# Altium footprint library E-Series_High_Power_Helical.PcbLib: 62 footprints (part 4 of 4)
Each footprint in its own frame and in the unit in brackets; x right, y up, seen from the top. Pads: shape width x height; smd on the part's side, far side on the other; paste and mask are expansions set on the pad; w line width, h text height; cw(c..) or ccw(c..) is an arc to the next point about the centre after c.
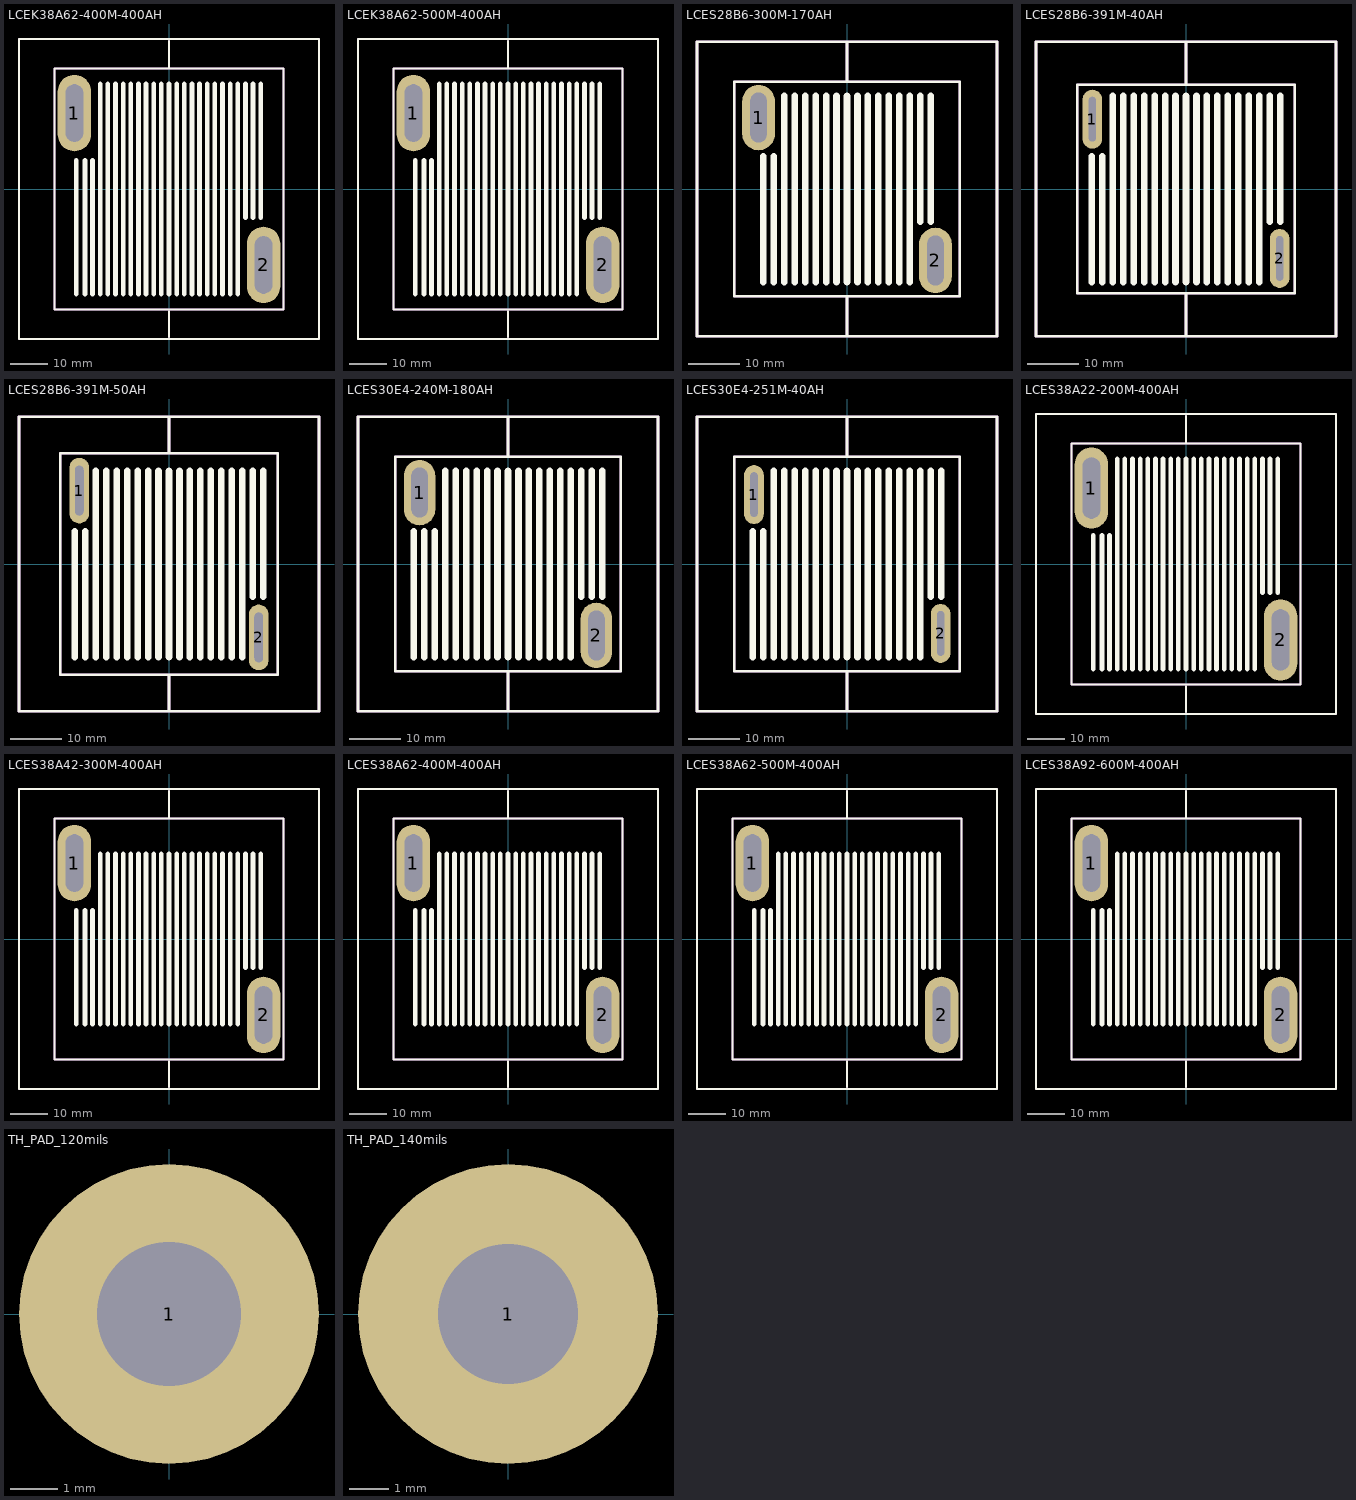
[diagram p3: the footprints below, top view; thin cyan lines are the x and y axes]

## LCEK38A62-400M-400AH [mil]
pads (2):
  oval 350x800 hole 185 slot 600 at 90 deg: 1(-990,795) 2(990,-795)
Top Overlay:
  lines w19.68: 0,-1550 0,-1280 ; 0,1260 0,1550 ; -1570,-1570 -1570,1570 1570,1570 1570,-1570 -1570,-1570 ; -1200,-1260 -1200,1260 1200,1260 1200,-1260 -1200,-1260
  lines w50: -970,-1100 -970,300 ; -880,-1100 -880,300 ; -800,-1100 -800,300 ; -720,-1100 -720,1100 ; -640,-1100 -640,1100 ; -560,-1100 -560,1100 ; -480,-1100 -480,1100 ; -400,-1100 -400,1100 ; -320,-1100 -320,1100 ; -240,-1100 -240,1100 ; -160,-1100 -160,1100 ; -80,-1100 -80,1100 ; 0,-1100 0,1100 ; 80,-1100 80,1100 ; 160,-1100 160,1100 ; 240,-1100 240,1100 ; 320,-1100 320,1100 ; 400,-1100 400,1100 ; 480,-1100 480,1100 ; 560,-1100 560,1100 ; 640,-1100 640,1100 ; 720,-1100 720,1100 ; 800,-300 800,1100 ; 880,-300 880,1100 ; 960,-300 960,1100
Components Top Assy:
  lines w19.68: 0,-1550 0,-1280 ; 0,1260 0,1550 ; -1570,-1570 1570,-1570 1570,1570 -1570,1570 -1570,-1570 ; -1200,-1260 1200,-1260 1200,1260 -1200,1260 -1200,-1260
  text "'.Designator'" at -938.15,-44.83 h400

## LCEK38A62-500M-400AH [mil]
pads (2):
  oval 350x800 hole 185 slot 600 at 90 deg: 1(-990,795) 2(990,-795)
Top Overlay:
  lines w19.68: 0,-1550 0,-1280 ; 0,1260 0,1550 ; -1570,-1570 1570,-1570 1570,1570 -1570,1570 -1570,-1570 ; -1200,-1260 1200,-1260 1200,1260 -1200,1260 -1200,-1260
  lines w50: -970,-1100 -970,300 ; -880,-1100 -880,300 ; -800,-1100 -800,300 ; -720,-1100 -720,1100 ; -640,-1100 -640,1100 ; -560,-1100 -560,1100 ; -480,-1100 -480,1100 ; -400,-1100 -400,1100 ; -320,-1100 -320,1100 ; -240,-1100 -240,1100 ; -160,-1100 -160,1100 ; -80,-1100 -80,1100 ; 0,-1100 0,1100 ; 80,-1100 80,1100 ; 160,-1100 160,1100 ; 240,-1100 240,1100 ; 320,-1100 320,1100 ; 400,-1100 400,1100 ; 480,-1100 480,1100 ; 560,-1100 560,1100 ; 640,-1100 640,1100 ; 720,-1100 720,1100 ; 800,-300 800,1100 ; 880,-300 880,1100 ; 960,-300 960,1100
Components Top Assy:
  lines w19.68: 0,-1550 0,-1280 ; 0,1260 0,1550 ; -1570,-1570 1570,-1570 1570,1570 -1570,1570 -1570,-1570 ; -1200,-1260 1200,-1260 1200,1260 -1200,1260 -1200,-1260
  text "'.Designator'" at -938.15,-44.83 h400

## LCES28B6-300M-170AH [mil]
pads (2):
  oval 250x500 hole 125 slot 380 at 90 deg: 1(-675,545) 2(675,-545)
Top Overlay:
  lines w19.68: 0,-1120 0,-820 ; 0,820 0,1120 ; -1145,-1125 -1145,1125 1145,1125 1145,-1125 -1145,-1125 ; -860,-820 -860,820 860,820 860,-820 -860,-820
  lines w50: -640,-710 -640,250 ; -560,-710 -560,250 ; -480,-710 -480,710 ; -400,-710 -400,710 ; -320,-710 -320,710 ; -240,-710 -240,710 ; -160,-710 -160,710 ; -80,-710 -80,710 ; 0,-710 0,710 ; 80,-710 80,710 ; 160,-710 160,710 ; 240,-710 240,710 ; 320,-710 320,710 ; 400,-710 400,710 ; 480,-710 480,710 ; 560,-250 560,710 ; 640,-250 640,710
Components Top Assy:
  lines w19.68: 0,-1120 0,-820 ; 0,820 0,1120 ; -1145,-1125 -1145,1125 1145,1125 1145,-1125 -1145,-1125 ; -860,-820 -860,820 860,820 860,-820 -860,-820
  text "'.Designator'" at -938.15,-44.83 h400

## LCES28B6-391M-40AH [mil]
pads (2):
  oval 150x450 hole 55 slot 340 at 90 deg: 1(-715,533) 2(715,-530)
Top Overlay:
  lines w19.68: 0,-1120 0,-795 ; 0,800 0,1120 ; -1145,-1125 1145,-1125 1145,1125 -1145,1125 -1145,-1125 ; -830,-795 830,-795 830,795 -830,795 -830,-795
  lines w50: -720,-710 -720,250 ; -640,-710 -640,250 ; -560,-710 -560,710 ; -480,-710 -480,710 ; -400,-710 -400,710 ; -320,-710 -320,710 ; -240,-710 -240,710 ; -160,-710 -160,710 ; -80,-710 -80,710 ; 0,-710 0,710 ; 80,-710 80,710 ; 160,-710 160,710 ; 240,-710 240,710 ; 320,-710 320,710 ; 400,-710 400,710 ; 480,-710 480,710 ; 560,-710 560,710 ; 640,-250 640,710 ; 720,-250 720,710
Components Top Assy:
  lines w19.68: 0,-1120 0,-795 ; 0,800 0,1120 ; -1145,-1125 1145,-1125 1145,1125 -1145,1125 -1145,-1125 ; -830,-795 830,-795 830,795 -830,795 -830,-795
  text "'.Designator'" at -950,-54.83 h400

## LCES28B6-391M-50AH [mil]
pads (2):
  oval 150x500 hole 65 slot 380 at 90 deg: 1(-685,560) 2(685,-560)
Top Overlay:
  lines w19.68: -830,840 -830,-845 830,-845 830,840 ; -830,845 830,845 ; 0,-1120 0,-845 ; 0,845 0,1120 ; -1145,-1125 -1145,1125 1145,1125 1145,-1125 -1145,-1125
  lines w50: -720,-710 -720,250 ; -640,-710 -640,250 ; -560,-710 -560,710 ; -480,-710 -480,710 ; -400,-710 -400,710 ; -320,-710 -320,710 ; -240,-710 -240,710 ; -160,-710 -160,710 ; -80,-710 -80,710 ; 0,-710 0,710 ; 80,-710 80,710 ; 160,-710 160,710 ; 240,-710 240,710 ; 320,-710 320,710 ; 400,-710 400,710 ; 480,-710 480,710 ; 560,-710 560,710 ; 640,-250 640,710 ; 720,-250 720,710
Components Top Assy:
  lines w19.68: -830,840 -830,-845 830,-845 830,840 ; -830,845 830,845 ; 0,-1120 0,-845 ; 0,845 0,1120 ; -1145,-1125 -1145,1125 1145,1125 1145,-1125 -1145,-1125
  text "'.Designator'" at -950,-54.83 h400

## LCES30E4-240M-180AH [mil]
pads (2):
  oval 240x500 hole 125 slot 380 at 90 deg: 1(-675,545) 2(675,-545)
Top Overlay:
  lines w19.68: 0,-1120 0,-820 ; 0,820 0,1120 ; -1145,-1125 -1145,1125 1145,1125 1145,-1125 -1145,-1125 ; -860,-820 -860,820 860,820 860,-820 -860,-820
  lines w50: -720,-710 -720,250 ; -640,-710 -640,250 ; -560,-710 -560,250 ; -480,-710 -480,710 ; -400,-710 -400,710 ; -320,-710 -320,710 ; -240,-710 -240,710 ; -160,-710 -160,710 ; -80,-710 -80,710 ; 0,-710 0,710 ; 80,-710 80,710 ; 160,-710 160,710 ; 240,-710 240,710 ; 320,-710 320,710 ; 400,-710 400,710 ; 480,-710 480,710 ; 560,-250 560,710 ; 640,-250 640,710 ; 720,-250 720,710
Components Top Assy:
  lines w19.68: 0,-1120 0,-820 ; 0,820 0,1120 ; -1145,-1125 1145,-1125 1145,1125 -1145,1125 -1145,-1125 ; -860,-820 860,-820 860,820 -860,820 -860,-820
  text "'.Designator'" at -938.15,-44.83 h400

## LCES30E4-251M-40AH [mil]
pads (2):
  oval 150x450 hole 55 slot 340 at 90 deg: 1(-710,530) 2(715,-530)
Top Overlay:
  lines w19.68: 0,-1120 0,-820 ; 0,820 0,1120 ; -1145,-1125 -1145,1125 1145,1125 1145,-1125 -1145,-1125 ; -860,-820 -860,820 860,820 860,-820 -860,-820
  lines w50: -720,-710 -720,250 ; -640,-710 -640,250 ; -560,-710 -560,710 ; -480,-710 -480,710 ; -400,-710 -400,710 ; -320,-710 -320,710 ; -240,-710 -240,710 ; -160,-710 -160,710 ; -80,-710 -80,710 ; 0,-710 0,710 ; 80,-710 80,710 ; 160,-710 160,710 ; 240,-710 240,710 ; 320,-710 320,710 ; 400,-710 400,710 ; 480,-710 480,710 ; 560,-710 560,710 ; 640,-250 640,710 ; 720,-250 720,710
Components Top Assy:
  lines w19.68: 0,-1120 0,-820 ; 0,820 0,1120 ; -1145,-1125 -1145,1125 1145,1125 1145,-1125 -1145,-1125 ; -860,-820 -860,820 860,820 860,-820 -860,-820
  text "'.Designator'" at -938.15,-44.83 h400

## LCES38A22-200M-400AH [mil]
pads (2):
  oval 350x850 hole 185 slot 640 at 90 deg: 1(-990,795) 2(990,-795)
Top Overlay:
  lines w19.68: 0,-1550 0,-1280 ; 0,1260 0,1550 ; -1570,-1570 1570,-1570 1570,1570 -1570,1570 -1570,-1570 ; -1200,-1260 1200,-1260 1200,1260 -1200,1260 -1200,-1260
  lines w50: -970,-1100 -970,300 ; -880,-1100 -880,300 ; -800,-1100 -800,300 ; -720,-1100 -720,1100 ; -640,-1100 -640,1100 ; -560,-1100 -560,1100 ; -480,-1100 -480,1100 ; -400,-1100 -400,1100 ; -320,-1100 -320,1100 ; -240,-1100 -240,1100 ; -160,-1100 -160,1100 ; -80,-1100 -80,1100 ; 0,-1100 0,1100 ; 80,-1100 80,1100 ; 160,-1100 160,1100 ; 240,-1100 240,1100 ; 320,-1100 320,1100 ; 400,-1100 400,1100 ; 480,-1100 480,1100 ; 560,-1100 560,1100 ; 640,-1100 640,1100 ; 720,-1100 720,1100 ; 800,-300 800,1100 ; 880,-300 880,1100 ; 960,-300 960,1100
Components Top Assy:
  lines w19.68: -1570,-1570 -1570,1570 ; -1570,-1570 1570,-1570 ; -1570,-1570 -1570,1570 ; -1570,-1570 1570,-1570 ; -1570,-1570 -1570,1570 ; -1570,-1570 1570,-1570 ; -1570,1570 1570,1570 ; -1570,1570 1570,1570 ; -1570,1570 1570,1570 ; -1200,-1260 -1200,1260 ; -1200,-1260 1200,-1260 ; -1200,-1260 -1200,1260 ; -1200,-1260 1200,-1260 ; -1200,-1260 -1200,1260 ; -1200,-1260 1200,-1260 ; -1200,1260 1200,1260 ; -1200,1260 1200,1260 ; -1200,1260 1200,1260 ; 0,-1550 0,-1280 ; 0,-1550 0,-1280 ; 0,-1550 0,-1280 ; 0,1260 0,1550 ; 0,1260 0,1550 ; 0,1260 0,1550 ; 1200,-1260 1200,1260 ; 1200,-1260 1200,1260 ; 1200,-1260 1200,1260 ; 1570,-1570 1570,1570 ; 1570,-1570 1570,1570 ; 1570,-1570 1570,1570
  text "'.Designator'" at -938.15,-44.83 h400

## LCES38A42-300M-400AH [mil]
pads (2):
  oval 350x800 hole 185 slot 600 at 90 deg: 1(-990,795) 2(990,-795)
Top Overlay:
  lines w19.68: 0,-1550 0,-1280 ; 0,1260 0,1550 ; -1570,-1570 1570,-1570 1570,1570 -1570,1570 -1570,-1570 ; -1200,-1260 1200,-1260 1200,1260 -1200,1260 -1200,-1260
  lines w50: -970,-890 -970,300 ; -880,-890 -880,300 ; -800,-890 -800,300 ; -720,-890 -720,890 ; -640,-890 -640,890 ; -560,-890 -560,890 ; -480,-890 -480,890 ; -400,-890 -400,890 ; -320,-890 -320,890 ; -240,-890 -240,890 ; -160,-890 -160,890 ; -80,-890 -80,890 ; 0,-890 0,890 ; 80,-890 80,890 ; 160,-890 160,890 ; 240,-890 240,890 ; 320,-890 320,890 ; 400,-890 400,890 ; 480,-890 480,890 ; 560,-890 560,890 ; 640,-890 640,890 ; 720,-890 720,890 ; 800,-300 800,890 ; 880,-300 880,890 ; 960,-300 960,890
Components Top Assy:
  lines w19.68: -1570,-1570 1570,-1570 ; -1570,-1570 -1570,1570 ; -1570,-1570 1570,-1570 ; -1570,-1570 -1570,1570 ; -1570,-1570 1570,-1570 ; -1570,-1570 -1570,1570 ; -1570,1570 1570,1570 ; -1570,1570 1570,1570 ; -1570,1570 1570,1570 ; -1200,-1260 1200,-1260 ; -1200,-1260 -1200,1260 ; -1200,-1260 1200,-1260 ; -1200,-1260 -1200,1260 ; -1200,-1260 1200,-1260 ; -1200,-1260 -1200,1260 ; -1200,1260 1200,1260 ; -1200,1260 1200,1260 ; -1200,1260 1200,1260 ; 0,-1550 0,-1280 ; 0,-1550 0,-1280 ; 0,-1550 0,-1280 ; 0,1260 0,1550 ; 0,1260 0,1550 ; 0,1260 0,1550 ; 1200,-1260 1200,1260 ; 1200,-1260 1200,1260 ; 1200,-1260 1200,1260 ; 1570,-1570 1570,1570 ; 1570,-1570 1570,1570 ; 1570,-1570 1570,1570
  text "'.Designator'" at -938.15,-44.83 h400

## LCES38A62-400M-400AH [mil]
pads (2):
  oval 350x800 hole 185 slot 600 at 90 deg: 1(-990,795) 2(990,-795)
Top Overlay:
  lines w19.68: -1570,-1570 1570,-1570 ; -1570,-1570 -1570,1570 ; -1570,-1570 1570,-1570 ; -1570,-1570 -1570,1570 ; -1570,-1570 1570,-1570 ; -1570,-1570 -1570,1570 ; -1570,-1570 -1570,1570 ; -1570,-1570 1570,-1570 ; -1570,1570 1570,1570 ; -1570,1570 1570,1570 ; -1570,1570 1570,1570 ; -1570,1570 1570,1570 ; -1200,-1260 1200,-1260 ; -1200,-1260 -1200,1260 ; -1200,-1260 1200,-1260 ; -1200,-1260 -1200,1260 ; -1200,-1260 1200,-1260 ; -1200,-1260 -1200,1260 ; -1200,-1260 -1200,1260 ; -1200,-1260 1200,-1260 ; -1200,1260 1200,1260 ; -1200,1260 1200,1260 ; -1200,1260 1200,1260 ; -1200,1260 1200,1260 ; 0,-1550 0,-1280 ; 0,-1550 0,-1280 ; 0,-1550 0,-1280 ; 0,-1550 0,-1280 ; 0,1260 0,1550 ; 0,1260 0,1550 ; 0,1260 0,1550 ; 0,1260 0,1550 ; 1200,-1260 1200,1260 ; 1200,-1260 1200,1260 ; 1200,-1260 1200,1260 ; 1200,-1260 1200,1260 ; 1570,-1570 1570,1570 ; 1570,-1570 1570,1570 ; 1570,-1570 1570,1570 ; 1570,-1570 1570,1570
  lines w50: -970,-890 -970,300 ; -880,-890 -880,300 ; -800,-890 -800,300 ; -720,-890 -720,890 ; -640,-890 -640,890 ; -560,-890 -560,890 ; -480,-890 -480,890 ; -400,-890 -400,890 ; -320,-890 -320,890 ; -240,-890 -240,890 ; -160,-890 -160,890 ; -80,-890 -80,890 ; 0,-890 0,890 ; 80,-890 80,890 ; 160,-890 160,890 ; 240,-890 240,890 ; 320,-890 320,890 ; 400,-890 400,890 ; 480,-890 480,890 ; 560,-890 560,890 ; 640,-890 640,890 ; 720,-890 720,890 ; 800,-300 800,890 ; 880,-300 880,890 ; 960,-300 960,890
Components Top Assy:
  lines w19.68: -1570,-1570 1570,-1570 ; -1570,-1570 -1570,1570 ; -1570,-1570 1570,-1570 ; -1570,-1570 -1570,1570 ; -1570,-1570 1570,-1570 ; -1570,-1570 -1570,1570 ; -1570,1570 1570,1570 ; -1570,1570 1570,1570 ; -1570,1570 1570,1570 ; -1200,-1260 1200,-1260 ; -1200,-1260 -1200,1260 ; -1200,-1260 1200,-1260 ; -1200,-1260 -1200,1260 ; -1200,-1260 1200,-1260 ; -1200,-1260 -1200,1260 ; -1200,1260 1200,1260 ; -1200,1260 1200,1260 ; -1200,1260 1200,1260 ; 0,-1550 0,-1280 ; 0,-1550 0,-1280 ; 0,-1550 0,-1280 ; 0,1260 0,1550 ; 0,1260 0,1550 ; 0,1260 0,1550 ; 1200,-1260 1200,1260 ; 1200,-1260 1200,1260 ; 1200,-1260 1200,1260 ; 1570,-1570 1570,1570 ; 1570,-1570 1570,1570 ; 1570,-1570 1570,1570
  text "'.Designator'" at -938.15,-44.83 h400

## LCES38A62-500M-400AH [mil]
pads (2):
  oval 350x800 hole 185 slot 600 at 90 deg: 1(-990,795) 2(990,-795)
Top Overlay:
  lines w19.68: -1570,-1570 -1570,1570 ; -1570,-1570 1570,-1570 ; -1570,-1570 -1570,1570 ; -1570,-1570 1570,-1570 ; -1570,-1570 -1570,1570 ; -1570,-1570 1570,-1570 ; -1570,1570 1570,1570 ; -1570,1570 1570,1570 ; -1570,1570 1570,1570 ; -1200,-1260 -1200,1260 ; -1200,-1260 1200,-1260 ; -1200,-1260 -1200,1260 ; -1200,-1260 1200,-1260 ; -1200,-1260 -1200,1260 ; -1200,-1260 1200,-1260 ; -1200,1260 1200,1260 ; -1200,1260 1200,1260 ; -1200,1260 1200,1260 ; 0,-1550 0,-1280 ; 0,-1550 0,-1280 ; 0,-1550 0,-1280 ; 0,1260 0,1550 ; 0,1260 0,1550 ; 0,1260 0,1550 ; 1200,-1260 1200,1260 ; 1200,-1260 1200,1260 ; 1200,-1260 1200,1260 ; 1570,-1570 1570,1570 ; 1570,-1570 1570,1570 ; 1570,-1570 1570,1570
  lines w50: -970,-890 -970,300 ; -880,-890 -880,300 ; -800,-890 -800,300 ; -720,-890 -720,890 ; -640,-890 -640,890 ; -560,-890 -560,890 ; -480,-890 -480,890 ; -400,-890 -400,890 ; -320,-890 -320,890 ; -240,-890 -240,890 ; -160,-890 -160,890 ; -80,-890 -80,890 ; 0,-890 0,890 ; 80,-890 80,890 ; 160,-890 160,890 ; 240,-890 240,890 ; 320,-890 320,890 ; 400,-890 400,890 ; 480,-890 480,890 ; 560,-890 560,890 ; 640,-890 640,890 ; 720,-890 720,890 ; 800,-300 800,890 ; 880,-300 880,890 ; 960,-300 960,890
Components Top Assy:
  lines w19.68: -1570,-1570 -1570,1570 ; -1570,-1570 1570,-1570 ; -1570,-1570 -1570,1570 ; -1570,-1570 1570,-1570 ; -1570,-1570 -1570,1570 ; -1570,-1570 1570,-1570 ; -1570,1570 1570,1570 ; -1570,1570 1570,1570 ; -1570,1570 1570,1570 ; -1200,-1260 -1200,1260 ; -1200,-1260 1200,-1260 ; -1200,-1260 -1200,1260 ; -1200,-1260 1200,-1260 ; -1200,-1260 -1200,1260 ; -1200,-1260 1200,-1260 ; -1200,1260 1200,1260 ; -1200,1260 1200,1260 ; -1200,1260 1200,1260 ; 0,-1550 0,-1280 ; 0,-1550 0,-1280 ; 0,-1550 0,-1280 ; 0,1260 0,1550 ; 0,1260 0,1550 ; 0,1260 0,1550 ; 1200,-1260 1200,1260 ; 1200,-1260 1200,1260 ; 1200,-1260 1200,1260 ; 1570,-1570 1570,1570 ; 1570,-1570 1570,1570 ; 1570,-1570 1570,1570
  text "'.Designator'" at -938.15,-44.83 h400

## LCES38A92-600M-400AH [mil]
pads (2):
  oval 350x800 hole 185 slot 600 at 90 deg: 1(-990,795) 2(990,-795)
Top Overlay:
  lines w19.68: 0,-1550 0,-1280 ; 0,1260 0,1550 ; -1570,-1570 1570,-1570 1570,1570 -1570,1570 -1570,-1570 ; -1200,-1260 1200,-1260 1200,1260 -1200,1260 -1200,-1260
  lines w50: -970,-890 -970,300 ; -880,-890 -880,300 ; -800,-890 -800,300 ; -720,-890 -720,890 ; -640,-890 -640,890 ; -560,-890 -560,890 ; -480,-890 -480,890 ; -400,-890 -400,890 ; -320,-890 -320,890 ; -240,-890 -240,890 ; -160,-890 -160,890 ; -80,-890 -80,890 ; 0,-890 0,890 ; 80,-890 80,890 ; 160,-890 160,890 ; 240,-890 240,890 ; 320,-890 320,890 ; 400,-890 400,890 ; 480,-890 480,890 ; 560,-890 560,890 ; 640,-890 640,890 ; 720,-890 720,890 ; 800,-300 800,890 ; 880,-300 880,890 ; 960,-300 960,890
Components Top Assy:
  lines w19.68: 0,-1550 0,-1280 ; 0,1260 0,1550 ; -1570,-1570 1570,-1570 1570,1570 -1570,1570 -1570,-1570 ; -1200,-1260 1200,-1260 1200,1260 -1200,1260 -1200,-1260
  text "'.Designator'" at -938.15,-44.83 h400

## TH_PAD_120mils [mil]
pads (1):
  round 250 hole 120: 1(0,0)

## TH_PAD_140mils [mil]
pads (1):
  round 300 / inner round 250 / far side round 250 hole 140: 1(0,0)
